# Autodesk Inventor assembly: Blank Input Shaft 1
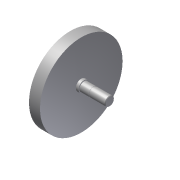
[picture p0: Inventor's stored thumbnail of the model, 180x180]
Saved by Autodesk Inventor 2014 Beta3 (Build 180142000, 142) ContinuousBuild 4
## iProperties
Created: 2011-01
Part Number: Blank Input Shaft 1
Document SubType Name: Assembly
Designer: Beta-8540w
ClientObjectVersion: 1
Author: Beta-8540w
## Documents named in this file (2)
- C:\Inventor 2014 Essentials\Assemblies\Chapter 09\Design Accelerators\Blank Input Shaft 1.iam
- C:\Inventor 2014 Essentials\Assemblies\Chapter 09\Design Accelerators\Blank Input Shaft 1.ipt
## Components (1 placed, 1 different names)
1. Blank Input Shaft 1:1
